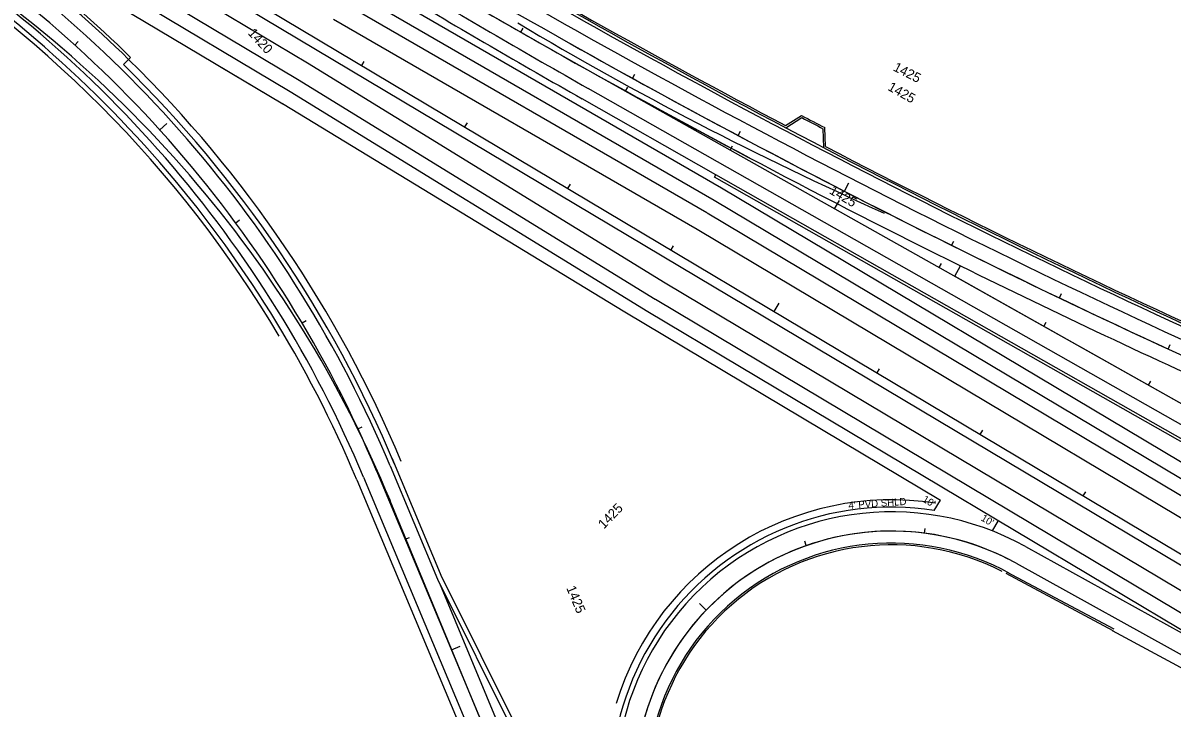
# Model space of a CAD drawing. Extents: x 2339272 to 2351734, y 366540 to 375057.
# Drawn here: x 2348051 to 2349008, y 368126 to 368697 of the extents above; entities that cross this region are included whole.
import ezdxf

# ---------------------------------------------------------------- set-up
doc = ezdxf.new("R2010")
doc.units = 0
for name, color, linetype in [('RD_HC_Cl', 7, 'Continuous'), ('RD_HC_CL_Rel', 7, 'Continuous'), ('RD_HC_Data_Tic', 7, 'Continuous'), ('RD_HC_Data_Tic_Rel', 7, 'Continuous'), ('RD_HC_TX_Rel_Sta50', 7, 'Continuous'), ('RD_HC_TX_Sta50', 7, 'Continuous'), ('RD_PD_Final_LnLine', 7, 'Continuous'), ('RD_PD_Final_TrvlWay', 7, 'Continuous'), ('RD_PD_FOC', 7, 'Continuous'), ('RD_PD_GR', 7, 'Continuous'), ('RD_PD_GrRail', 7, 'Continuous'), ('RD_PD_MedBWall', 7, 'Continuous'), ('RD_PD_MedGR', 7, 'Continuous'), ('RD_PD_NOISE-WALL-GM', 7, 'Continuous'), ('RD_PD_PaveShd', 7, 'Continuous'), ('RD_PD_WallCut', 7, 'Continuous')]:
    doc.layers.add(name, color=color, linetype=linetype)

msp = doc.modelspace()

# ---------------------------------------------------------------- linework, layer by layer
at = {"layer": 'RD_HC_Cl'}
msp.add_line((2346281.57, 369885.43), (2351112.4, 367003.22), dxfattribs=at)
msp.add_arc((2349948.99, 371187.23), 2900, 239.17851, 245.9774, dxfattribs=at)
msp.add_arc((2349948.99, 371187.23), 2900, 239.17851, 245.9774, dxfattribs=at)
msp.add_arc((2349948.99, 371187.23), 2900, 239.17851, 245.9774, dxfattribs=at)
msp.add_arc((2349948.99, 371187.23), 2900, 239.17851, 245.9774, dxfattribs=at)
at = {"layer": 'RD_HC_CL_Rel'}
for p, q in [((2348500.93, 368669.16), (2349129.79, 368315.43)), ((2348345.74, 368322.92), (2348612.9, 367684.58))]:
    msp.add_line(p, q, dxfattribs=at)
for centre, radius, start, end in [((2347423.27, 367936.84), 1000, 22.71075, 59.17851), ((2351938.58, 374780.68), 7012, 239.178507, 240.642806), ((2351938.58, 374780.68), 7000, 240.642806, 245.882475), ((2348774.65, 368059.29), 214.01, 62.97341, 174.06692)]:
    msp.add_arc(centre, radius, start, end, dxfattribs=at)
at = {"layer": 'RD_HC_Data_Tic'}
for p, q in [((2348333.23, 368661.35), (2348335.28, 368664.79)), ((2348419.11, 368610.11), (2348421.16, 368613.55)), ((2348504.99, 368558.88), (2348507.04, 368562.31)), ((2348590.86, 368507.64), (2348592.91, 368511.08)), ((2348676.74, 368456.4), (2348680.84, 368463.27)), ((2348762.62, 368405.17), (2348764.67, 368408.6)), ((2348848.49, 368353.93), (2348850.54, 368357.37)), ((2348934.37, 368302.69), (2348936.42, 368306.13))]:
    msp.add_line(p, q, dxfattribs=at)
at = {"layer": 'RD_HC_Data_Tic_Rel'}
for p, q in [((2348465.77, 368689.06), (2348467.76, 368692.54)), ((2348094.26, 368678.31), (2348096.95, 368681.27)), ((2348558.88, 368650.62), (2348560.81, 368654.12)), ((2348552.88, 368639.94), (2348554.84, 368643.42)), ((2348164.93, 368607.62), (2348170.87, 368612.98)), ((2348646.79, 368602.96), (2348648.68, 368606.49)), ((2348640.03, 368590.91), (2348641.99, 368594.4)), ((2348735.38, 368556.57), (2348739.04, 368563.68)), ((2348727.19, 368541.88), (2348731.11, 368548.86)), ((2348228.19, 368530.22), (2348231.41, 368532.6)), ((2348824.62, 368511.45), (2348826.4, 368515.03)), ((2348814.35, 368492.86), (2348816.31, 368496.35)), ((2348914.49, 368467.6), (2348916.22, 368471.21)), ((2348283.41, 368446.9), (2348286.85, 368448.94)), ((2348901.51, 368443.83), (2348903.47, 368447.32)), ((2349004.99, 368425.05), (2349006.66, 368428.68)), ((2348988.67, 368394.81), (2348990.63, 368398.3)), ((2348330.04, 368358.48), (2348333.66, 368360.17)), ((2348802.14, 368271.53), (2348802.65, 368275.49)), ((2348369.34, 368266.54), (2348373.03, 368268.08)), ((2348703.59, 368261.16), (2348702.26, 368264.93)), ((2348620.28, 368207.51), (2348614.51, 368213.05)), ((2348407.94, 368174.29), (2348415.32, 368177.38))]:
    msp.add_line(p, q, dxfattribs=at)
at = {"layer": 'RD_PD_Final_LnLine'}
for p, q in [((2346262.53, 369853.51), (2348279.79, 368649.96)), ((2348317.78, 368713.85), (2348620.78, 368538.7)), ((2348279.7, 368650.01), (2348577.74, 368466.56)), ((2348620.92, 368538.62), (2351133.92, 367039.29)), ((2348577.88, 368466.48), (2351090.88, 366967.15)), ((2348343.52, 368328.22), (2348585.38, 367750.35)), ((2348611.02, 367683.86), (2348357, 368298.46)), ((2348611.02, 367683.86), (2348357, 368298.46)), ((2348611.02, 367683.86), (2348357, 368298.46)), ((2348611.02, 367683.86), (2348357, 368298.46)), ((2348397.99, 368229.79), (2348466.75, 368064.86))]:
    msp.add_line(p, q, dxfattribs=at)
for centre, radius, start, end in [((2347423.27, 367936.84), 1000, 22.71075, 59.17851), ((2347432.83, 367916.49), 1000, 22.45591, 59.17851), ((2347432.83, 367916.49), 1000, 22.45591, 59.17851), ((2347432.83, 367916.49), 1000, 22.45591, 59.17851), ((2347432.83, 367916.49), 1000, 22.45591, 59.17851), ((2351938.58, 374780.68), 7000, 239.178507, 245.882475), ((2351938.58, 374780.68), 7012, 239.178507, 242.089491), ((2351938.58, 374780.68), 7012, 240.642806, 243.703137)]:
    msp.add_arc(centre, radius, start, end, dxfattribs=at)
at = {"layer": 'RD_PD_Final_TrvlWay'}
for p, q in [((2346256.38, 369843.21), (2348273.55, 368639.71)), ((2348323.79, 368724.24), (2348626.93, 368549.01)), ((2348273.55, 368639.71), (2348571.59, 368456.26)), ((2349153.03, 368283.92), (2348521.76, 368642.31)), ((2348626.93, 368549.01), (2350811.17, 367245.82)), ((2348827.21, 368485.63), (2348832.11, 368494.34)), ((2348827.21, 368485.63), (2349129.79, 368315.43)), ((2348571.59, 368456.26), (2349076.83, 368154.82)), ((2348356.81, 368327.55), (2348396.32, 368233.15)), ((2348334.67, 368318.29), (2348438.16, 368071.02)), ((2348863.44, 368282.13), (2348858.32, 368273.54)), ((2348886.11, 368260.49), (2349076.83, 368154.82)), ((2348878.36, 368246.49), (2349178.28, 368080.32)), ((2348396.32, 368233.15), (2348478.33, 368068.28))]:
    msp.add_line(p, q, dxfattribs=at)
for centre, radius, start, end in [((2347423.27, 367936.84), 1012, 22.71075, 59.17851), ((2347423.27, 367936.84), 988, 22.71075, 59.17851), ((2351938.58, 374780.68), 6988, 239.178507, 245.882475), ((2352567.57, 375768.6), 8194.67, 239.178507, 240.415096), ((2351938.58, 374780.68), 7012, 243.703137, 245.882475), ((2348774.64, 368059.31), 230, 61.0108, 285.1623), ((2348774.64, 368059.31), 214, 61.0108, 285.16043)]:
    msp.add_arc(centre, radius, start, end, dxfattribs=at)
at = {"layer": 'RD_PD_FOC'}
msp.add_line((2348869.75, 368238.08), (2348959.09, 368190.55), dxfattribs=at)
msp.add_arc((2348774.64, 368059.31), 202.5, 62.97341, 267.67657, dxfattribs=at)
at = {"layer": 'RD_PD_GR'}
for centre, radius, start, end in [((2347423.27, 367936.84), 978, 30.66777, 59.17851), ((2347423.27, 367936.84), 1022, 22.71075, 45.55608), ((2348774.64, 368059.31), 240, 81.15571, 162.94062)]:
    msp.add_arc(centre, radius, start, end, dxfattribs=at)
at = {"layer": 'RD_PD_GrRail'}
msp.add_line((2349187.97, 368066.39), (2348958.64, 368190.22), dxfattribs=at)
at = {"layer": 'RD_PD_MedBWall'}
msp.add_line((2348140.52, 368668.15), (2348138.89, 368666.49), dxfattribs=at)
for centre, radius, start, end in [((2347423.27, 367936.84), 1022, 45.55608, 59.17851), ((2347423.27, 367936.84), 1024.33, 45.55608, 59.17851), ((2351938.58, 374780.68), 6975.67, 239.178507, 245.882475), ((2351938.58, 374780.68), 6978, 239.178507, 245.882475)]:
    msp.add_arc(centre, radius, start, end, dxfattribs=at)
at = {"layer": 'RD_PD_MedGR'}
msp.add_line((2347144.89, 369361.04), (2349123.23, 368180.7), dxfattribs=at)
at = {"layer": 'RD_PD_NOISE-WALL-GM'}
for p, q in [((2348686.37, 368611.22), (2348699.71, 368619.65)), ((2348686.44, 368609.49), (2348699.78, 368617.92)), ((2348718.17, 368592.88), (2348717.5, 368608.64)), ((2348719.63, 368593.81), (2348718.96, 368609.57))]:
    msp.add_line(p, q, dxfattribs=at)
for radius, start, end in [(6974.17, 239.178507, 242.204196), (6960.5, 242.268979, 242.447832), (6962, 242.276108, 242.440704), (6974.17, 242.512616, 245.882475)]:
    msp.add_arc((2351938.58, 374780.68), radius, start, end, dxfattribs=at)
at = {"layer": 'RD_PD_PaveShd'}
for p, q in [((2346250.23, 369832.9), (2348267.49, 368629.35)), ((2347107.36, 369368.09), (2348288.04, 368663.67)), ((2348330.01, 368734.5), (2348633, 368559.35)), ((2348309.77, 368700), (2348612.75, 368524.86)), ((2348134.69, 368662.2), (2348138.89, 368666.49)), ((2348216.02, 368660.06), (2348267.49, 368629.35)), ((2348288.09, 368663.64), (2348586.1, 368480.21)), ((2348267.03, 368629.63), (2348552.32, 368456.11)), ((2348628.23, 368570.36), (2348516.82, 368633.61)), ((2348633, 368559.35), (2349320.08, 368149.43)), ((2348612.75, 368524.86), (2349277.31, 368128.37)), ((2348586.11, 368480.2), (2349221.38, 368101.18)), ((2348552.32, 368456.11), (2348815.37, 368299.17)), ((2348358.28, 368334.4), (2348400.01, 368234.69)), ((2348329.13, 368315.97), (2348432.54, 368068.89)), ((2348810.25, 368290.58), (2348815.37, 368299.17)), ((2348399.9, 368234.93), (2348481.97, 368069.95)), ((2348870.46, 368239.4), (2348959.8, 368191.87))]:
    msp.add_line(p, q, dxfattribs=at)
for centre, radius, start, end in [((2351938.58, 374780.68), 6978, 239.178507, 245.882475), ((2347423.27, 367936.84), 982, 22.71075, 59.17851), ((2352567.57, 375768.6), 8204.67, 239.178507, 240.415096), ((2347423.27, 367936.84), 1016, 22.71075, 45.55608), ((2348774.64, 368059.31), 234, 81.2484, 268.00355), ((2348774.64, 368059.31), 204, 61.0108, 267.6974)]:
    msp.add_arc(centre, radius, start, end, dxfattribs=at)
at = {"layer": 'RD_PD_WallCut'}
for p, q in [((2348627.08, 368568.34), (2348628.23, 368570.36)), ((2349148.1, 368275.22), (2348628.23, 368570.36)), ((2349148.1, 368275.22), (2348628.23, 368570.36)), ((2349146.94, 368273.19), (2348627.08, 368568.34))]:
    msp.add_line(p, q, dxfattribs=at)

# ---------------------------------------------------------------- texts
at = {"layer": 'RD_HC_TX_Rel_Sta50'}
for s, rotation, p in [('1420', 312.12693, (2348237.86, 368687.99)), ('1425', 332.76766, (2348775.31, 368657.48)), ('1425', 330.64281, (2348770.83, 368641.25)), ('1425', 46.16536, (2348534.98, 368274.61)), ('1425', 292.71075, (2348503.45, 368225.84))]:
    msp.add_text(s, height=8, rotation=rotation, dxfattribs=at).set_placement(p)
at = {"layer": 'RD_HC_TX_Sta50'}
msp.add_text('1425', height=8, rotation=329.17851, dxfattribs=at).set_placement((2348722.08, 368555.11))
at = {"layer": 'RD_PD_Final_TrvlWay'}
for s, rotation, p in [("10'", 329.17851, (2348799.78, 368298.24)), ("4' PVD SHLD", 3.96983, (2348738.94, 368291.77)), ("10'", 329.17851, (2348848.56, 368282.53))]:
    msp.add_text(s, height=6, rotation=rotation, dxfattribs=at).set_placement(p)

doc.saveas('drawing.dxf')
